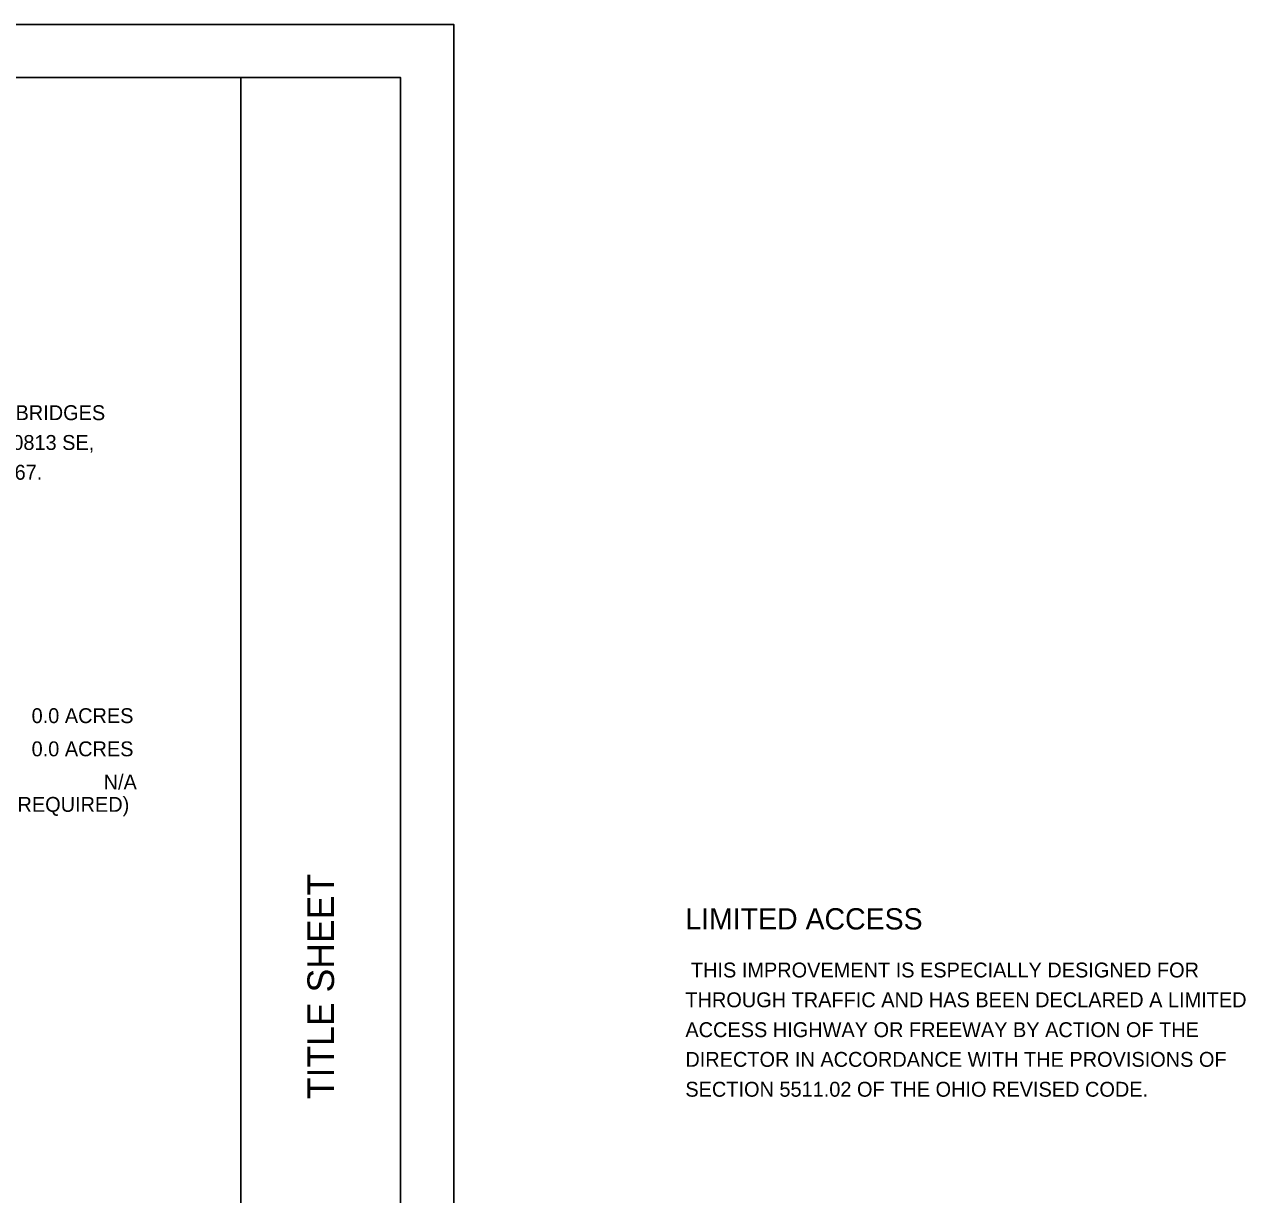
# Model space of a CAD drawing. Extents: x -10 to 89.7, y -4.8 to 22.
# Drawn here: x 29.97 to 41.44, y 11 to 22 of the extents above; entities that cross this region are included whole.
import ezdxf

# ---------------------------------------------------------------- set-up
doc = ezdxf.new("R2010")
doc.units = 0
for name, color, linetype in [('GM_X_Minor_Lake', 7, 'Continuous'), ('GM_X_Minor_River', 7, 'Continuous'), ('GM_X_Minor_River_Text', 7, 'Continuous'), ('SH_Text', 7, 'Continuous')]:
    doc.layers.add(name, color=color, linetype=linetype)

msp = doc.modelspace()

# ---------------------------------------------------------------- linework, layer by layer
at = {"layer": 'GM_X_Minor_River'}
msp.add_line((32, 0.5), (32, 21.5), dxfattribs=at)
msp.add_lwpolyline([(1.5, 21.5), (33.5, 21.5), (33.5, 0.5), (1.5, 0.5)], close=True, dxfattribs=at)
at = {"layer": 'SH_Text'}
msp.add_lwpolyline([(0, 0), (34, 0), (34, 22), (0, 22)], close=True, dxfattribs=at)

# ---------------------------------------------------------------- texts
at = {"layer": 'GM_X_Minor_Lake'}
msp.add_text('TITLE SHEET', height=0.25, rotation=90, dxfattribs=at).set_placement((32.875, 11.897))
at = {"layer": 'GM_X_Minor_River_Text'}
for s, height, p in [('PAINT THE STRUCTURAL STEEL ON MULTIPLE MAINLINE BRIDGES ', 0.14, (24.66, 18.28)), ('ALONG THE I-71/I-480 CORRIDOR: CUY-17-0449, CUY-237-0813 SE,', 0.14, (24.66, 18)), ('CUY-480-0856 ES, CUY-71-0994, CUY-71-1188 & CUY-71-0467.', 0.14, (24.66, 17.72)), ('0.0 ACRES', 0.14, (30.033, 15.432)), ('0.0 ACRES', 0.14, (30.033, 15.12)), ('N/A', 0.14, (30.71, 14.808)), ('(NOI NOT REQUIRED)', 0.14, (29.006, 14.598)), ('LIMITED ACCESS', 0.2, (36.177, 13.492)), (' THIS IMPROVEMENT IS ESPECIALLY DESIGNED FOR', 0.14, (36.177, 13.041)), ('THROUGH TRAFFIC AND HAS BEEN DECLARED A LIMITED', 0.14, (36.177, 12.761)), ('ACCESS HIGHWAY OR FREEWAY BY ACTION OF THE', 0.14, (36.177, 12.48)), ('DIRECTOR IN ACCORDANCE WITH THE PROVISIONS OF', 0.14, (36.177, 12.201)), ('SECTION 5511.02 OF THE OHIO REVISED CODE.', 0.14, (36.177, 11.92))]:
    msp.add_text(s, height=height, dxfattribs=at).set_placement(p)

doc.saveas('drawing.dxf')
